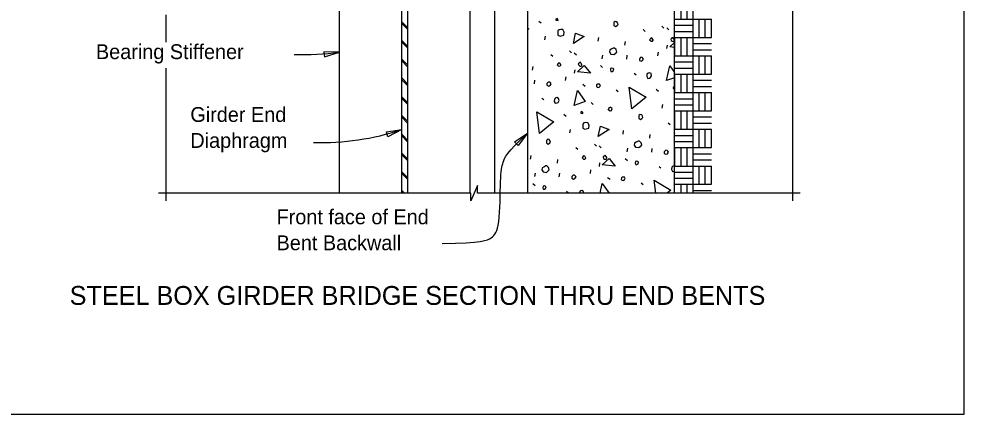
# Model space of a CAD drawing. Extents: x 112544 to 112597.1, y 111084 to 111107.1.
# Drawn here: x 112565.15 to 112574.78, y 111085.9 to 111089.92 of the extents above; entities that cross this region are included whole.
import ezdxf

# ---------------------------------------------------------------- set-up
doc = ezdxf.new("R2010")
doc.units = 0
for name, color, linetype in [('ActivePts-ConstElements', 7, 'Continuous'), ('Dimension', 7, 'Continuous'), ('Miscellaneous', 7, 'Continuous'), ('SteelGirder', 7, 'Continuous'), ('SupstrConc', 7, 'Continuous'), ('TextStructures', 7, 'Continuous')]:
    doc.layers.add(name, color=color, linetype=linetype)

msp = doc.modelspace()

# ---------------------------------------------------------------- linework, layer by layer
at = {"layer": 'ActivePts-ConstElements'}
msp.add_lwpolyline([(112543.9918, 111085.9039), (112574.7797, 111085.9039), (112574.7797, 111105.3634), (112543.9918, 111105.3634)], close=True, dxfattribs=at)
at = {"layer": 'Dimension'}
for points in [[(112573.0332, 111088.0729), (112573.0332, 111090.2426)], [(112566.6473, 111089.6865), (112566.6473, 111089.9653)], [(112566.6473, 111088.0729), (112566.6473, 111089.4223)], [(112573.1107, 111088.1504), (112569.8203, 111088.1504), (112569.8203, 111088.2279), (112569.7865, 111088.1504), (112569.7528, 111088.0729), (112569.7528, 111088.1504), (112566.5697, 111088.1504)]]:
    msp.add_lwpolyline(points, dxfattribs=at)
for points in [[(112568.413, 111089.5866), (112568.2547, 111089.5912), (112568.262, 111089.5388)], [(112569.0485, 111088.7986), (112568.9082, 111088.725), (112568.8918, 111088.7753)], [(112570.3297, 111088.7631), (112570.2358, 111088.6355), (112570.199, 111088.6735)]]:
    msp.add_lwpolyline(points, close=True, dxfattribs=at)
for centre, start, end in [((112568.0497, 111092.1885), 267.88954, 277.94853), ((112568.2255, 111091.2935), 268.34066, 288.25581)]:
    msp.add_arc(centre, 2.6271, start, end, dxfattribs=at)
msp.add_open_spline([(112569.4599, 111087.6403), (112569.8663, 111087.6456), (112569.9716, 111087.6958), (112570.0513, 111087.7852), (112570.0513, 111088.3406), (112570.0777, 111088.4633), (112570.1154, 111088.5614), (112570.3297, 111088.7631)], degree=3, dxfattribs=at)
at = {"layer": 'Miscellaneous'}
for p, q in [((112572.0185, 111089.9229), (112572.0185, 111090.2966)), ((112571.8922, 111090.1104), (112571.8922, 111089.9229)), ((112571.9547, 111090.1104), (112571.9547, 111089.9229)), ((112569.1109, 111089.8341), (112569.0485, 111089.8965)), ((112570.4465, 111089.9029), (112570.4699, 111089.8832)), ((112571.8297, 111089.9229), (112572.0185, 111089.9229)), ((112572.0185, 111089.5491), (112572.0185, 111089.9229)), ((112572.0185, 111089.9229), (112572.2047, 111089.9229)), ((112572.0797, 111089.7366), (112572.0797, 111089.9229)), ((112572.1422, 111089.7366), (112572.1422, 111089.9229)), ((112572.2047, 111089.7366), (112572.2047, 111089.9229)), ((112569.1109, 111089.8164), (112569.0485, 111089.8788)), ((112571.5105, 111089.8152), (112571.5308, 111089.7974)), ((112571.7003, 111089.8506), (112571.7212, 111089.8303)), ((112571.7491, 111089.8326), (112571.7701, 111089.8123)), ((112571.8297, 111089.8604), (112572.0185, 111089.8604)), ((112571.8297, 111089.7979), (112572.0185, 111089.7979)), ((112569.1109, 111089.6432), (112569.0485, 111089.7056)), ((112570.508, 111089.7123), (112570.514, 111089.7475)), ((112571.0504, 111089.6971), (112571.0558, 111089.7348)), ((112571.8297, 111089.7366), (112572.2047, 111089.7366)), ((112571.8297, 111089.7366), (112571.8297, 111089.5491)), ((112571.8922, 111089.7366), (112571.8922, 111089.5491)), ((112571.9547, 111089.7366), (112571.9547, 111089.5491)), ((112569.1109, 111089.6255), (112569.0485, 111089.6879)), ((112571.3227, 111089.6562), (112571.3282, 111089.6939)), ((112571.7508, 111089.6234), (112571.7569, 111089.6587)), ((112572.0185, 111089.6741), (112572.2047, 111089.6741)), ((112572.0185, 111089.6116), (112572.2047, 111089.6116)), ((112569.1109, 111089.4523), (112569.0485, 111089.5147)), ((112570.5687, 111089.5629), (112570.589, 111089.545)), ((112570.7585, 111089.5982), (112570.7795, 111089.578)), ((112570.8073, 111089.5803), (112570.8283, 111089.56)), ((112571.0928, 111089.5196), (112571.0988, 111089.5548)), ((112571.3421, 111089.5165), (112571.3475, 111089.5542)), ((112571.6593, 111089.5497), (112571.6647, 111089.5874)), ((112571.8297, 111089.5491), (112572.0185, 111089.5491)), ((112572.0185, 111089.5491), (112572.2047, 111089.5491)), ((112572.0185, 111089.1754), (112572.0185, 111089.5491)), ((112572.0797, 111089.3629), (112572.0797, 111089.5491)), ((112572.1422, 111089.3629), (112572.1422, 111089.5491)), ((112572.2047, 111089.3629), (112572.2047, 111089.5491)), ((112569.1109, 111089.4346), (112569.0485, 111089.497)), ((112570.3809, 111089.4039), (112570.3864, 111089.4416)), ((112571.0727, 111089.4495), (112571.0961, 111089.4299)), ((112571.8297, 111089.4866), (112572.0185, 111089.4866)), ((112571.8297, 111089.4241), (112572.0185, 111089.4241)), ((112569.1109, 111089.2613), (112569.0485, 111089.3237)), ((112570.7175, 111089.2974), (112570.7229, 111089.335)), ((112570.809, 111089.3711), (112570.8151, 111089.4063)), ((112571.4173, 111089.371), (112571.4369, 111089.3555)), ((112571.8297, 111089.3629), (112572.2047, 111089.3629)), ((112571.8297, 111089.3629), (112571.8297, 111089.1754)), ((112571.8922, 111089.3629), (112571.8922, 111089.1754)), ((112571.9547, 111089.3629), (112571.9547, 111089.1754)), ((112569.1109, 111089.2437), (112569.0485, 111089.3061)), ((112570.4003, 111089.2641), (112570.4057, 111089.3018)), ((112570.8934, 111089.2591), (112570.9192, 111089.2401)), ((112572.0185, 111089.3004), (112572.2047, 111089.3004)), ((112572.0185, 111089.2379), (112572.2047, 111089.2379)), ((112569.1109, 111089.0704), (112569.0485, 111089.1328)), ((112571.2345, 111089.203), (112571.2548, 111089.1851)), ((112571.642, 111089.2086), (112571.6653, 111089.189)), ((112571.8297, 111089.1754), (112572.0185, 111089.1754)), ((112572.0185, 111088.8016), (112572.0185, 111089.1754)), ((112572.0185, 111089.1754), (112572.2047, 111089.1754)), ((112572.0797, 111088.9891), (112572.0797, 111089.1754)), ((112572.1422, 111088.9891), (112572.1422, 111089.1754)), ((112572.2047, 111088.9891), (112572.2047, 111089.1754)), ((112569.1109, 111089.0527), (112569.0485, 111089.1151)), ((112570.4755, 111089.1186), (112570.4952, 111089.1032)), ((112570.9796, 111089.0725), (112571.0006, 111089.0523)), ((112571.7034, 111089.018), (112571.7095, 111089.0533)), ((112571.8297, 111089.1129), (112572.0185, 111089.1129)), ((112571.8297, 111089.0504), (112572.0185, 111089.0504)), ((112569.1109, 111088.8795), (112569.0485, 111088.9419)), ((112570.7002, 111088.9563), (112570.7236, 111088.9366)), ((112571.8297, 111088.9891), (112572.2047, 111088.9891)), ((112571.8297, 111088.9891), (112571.8297, 111088.8016)), ((112571.8922, 111088.9891), (112571.8922, 111088.8016)), ((112571.9547, 111088.9891), (112571.9547, 111088.8016)), ((112569.1109, 111088.8618), (112569.0485, 111088.9242)), ((112571.7641, 111088.8686), (112571.7844, 111088.8508)), ((112572.0185, 111088.9266), (112572.2047, 111088.9266)), ((112572.0185, 111088.8641), (112572.2047, 111088.8641)), ((112569.1109, 111088.6886), (112569.0485, 111088.751)), ((112570.7616, 111088.7657), (112570.7677, 111088.8009)), ((112571.304, 111088.7505), (112571.3094, 111088.7882)), ((112571.5764, 111088.7096), (112571.5818, 111088.7473)), ((112571.8297, 111088.8016), (112572.0185, 111088.8016)), ((112571.8297, 111088.7391), (112572.0185, 111088.7391)), ((112572.0185, 111088.8016), (112572.2047, 111088.8016)), ((112572.0185, 111088.4279), (112572.0185, 111088.8016)), ((112572.0797, 111088.6154), (112572.0797, 111088.8016)), ((112572.1422, 111088.6154), (112572.1422, 111088.8016)), ((112572.2047, 111088.6154), (112572.2047, 111088.8016)), ((112569.1109, 111088.6709), (112569.0485, 111088.7333)), ((112571.0122, 111088.6516), (112571.0331, 111088.6314)), ((112571.8297, 111088.6766), (112572.0185, 111088.6766)), ((112569.1109, 111088.4977), (112569.0485, 111088.5601)), ((112570.8223, 111088.6163), (112570.8426, 111088.5984)), ((112571.061, 111088.6336), (112571.0819, 111088.6134)), ((112571.3464, 111088.573), (112571.3525, 111088.6082)), ((112571.5957, 111088.5699), (112571.6011, 111088.6076)), ((112571.8297, 111088.6154), (112572.2047, 111088.6154)), ((112571.8297, 111088.6154), (112571.8297, 111088.4279)), ((112571.8922, 111088.6154), (112571.8922, 111088.4279)), ((112571.9547, 111088.6154), (112571.9547, 111088.4279)), ((112572.0185, 111088.5529), (112572.2047, 111088.5529)), ((112569.1109, 111088.48), (112569.0485, 111088.5424)), ((112570.3622, 111088.4982), (112570.3677, 111088.5359)), ((112570.6346, 111088.4573), (112570.64, 111088.495)), ((112571.0627, 111088.4245), (112571.0687, 111088.4597)), ((112571.3264, 111088.5029), (112571.3497, 111088.4833)), ((112572.0185, 111088.4904), (112572.2047, 111088.4904)), ((112569.1109, 111088.3067), (112569.0485, 111088.3691)), ((112569.1109, 111088.2891), (112569.0485, 111088.3515)), ((112570.4046, 111088.3206), (112570.4107, 111088.3559)), ((112570.6539, 111088.3175), (112570.6593, 111088.3552)), ((112570.9711, 111088.3508), (112570.9766, 111088.3884)), ((112571.6709, 111088.4244), (112571.6906, 111088.4089)), ((112571.8297, 111088.4279), (112572.0185, 111088.4279)), ((112571.8297, 111088.3654), (112572.0185, 111088.3654)), ((112572.0185, 111088.4279), (112572.2047, 111088.4279)), ((112572.0185, 111088.1504), (112572.0185, 111088.4279)), ((112572.0797, 111088.2416), (112572.0797, 111088.4279)), ((112572.1422, 111088.2416), (112572.1422, 111088.4279)), ((112572.2047, 111088.2416), (112572.2047, 111088.4279)), ((112571.147, 111088.3125), (112571.1728, 111088.2935)), ((112571.4882, 111088.2564), (112571.5085, 111088.2385)), ((112571.8297, 111088.3029), (112572.0185, 111088.3029)), ((112569.0764, 111088.1504), (112569.0485, 111088.1782)), ((112569.0587, 111088.1504), (112569.0485, 111088.1605)), ((112570.3846, 111088.2505), (112570.408, 111088.2309)), ((112570.7291, 111088.172), (112570.7488, 111088.1566)), ((112571.8297, 111088.2416), (112572.2047, 111088.2416)), ((112571.8922, 111088.2417), (112571.8922, 111088.1504)), ((112571.9547, 111088.2417), (112571.9547, 111088.1504)), ((112572.0185, 111088.1791), (112572.2047, 111088.1791))]:
    msp.add_line(p, q, dxfattribs=at)
for points in [[(112570.6204, 111089.9106), (112570.6417, 111089.9086), (112570.6391, 111089.9182), (112570.6311, 111089.929), (112570.6203, 111089.9209), (112570.6204, 111089.9106)], [(112571.211, 111089.8799), (112571.2107, 111089.8617), (112571.2273, 111089.8481), (112571.2429, 111089.8574), (112571.2531, 111089.8679), (112571.2498, 111089.88), (112571.2405, 111089.8956), (112571.224, 111089.899), (112571.2115, 111089.8878), (112571.211, 111089.8799)], [(112570.3297, 111089.8317), (112570.3436, 111089.8235), (112570.3297, 111089.8121)], [(112570.6393, 111089.8018), (112570.6406, 111089.7582), (112570.6614, 111089.7482), (112570.6735, 111089.7514), (112570.7, 111089.7586), (112570.7043, 111089.7908), (112570.69, 111089.8154), (112570.6711, 111089.8181), (112570.6518, 111089.8129), (112570.6393, 111089.8018)], [(112570.7979, 111089.6735), (112570.8209, 111089.7806), (112570.9083, 111089.7445), (112570.7979, 111089.6735)], [(112571.5747, 111089.7108), (112571.5889, 111089.6965), (112571.604, 111089.698), (112571.6117, 111089.7078), (112571.6104, 111089.7126), (112571.6017, 111089.7258), (112571.5901, 111089.7305), (112571.5824, 111089.7206), (112571.5747, 111089.7108)], [(112571.7937, 111089.7048), (112571.8035, 111089.6971), (112571.8169, 111089.6955), (112571.8253, 111089.7029), (112571.8251, 111089.7132), (112571.8194, 111089.7246), (112571.8114, 111089.7354), (112571.7982, 111089.7267), (112571.7898, 111089.7193), (112571.7937, 111089.7048)], [(112571.165, 111089.5881), (112571.1787, 111089.5659), (112571.2109, 111089.5616), (112571.2402, 111089.5875), (112571.2337, 111089.6117), (112571.2165, 111089.6278), (112571.2037, 111089.6269), (112571.1833, 111089.6163), (112571.1677, 111089.6069), (112571.165, 111089.5881)], [(112571.7803, 111089.6391), (112571.8297, 111089.685)], [(112571.8297, 111089.634), (112571.7803, 111089.6391)], [(112571.4706, 111089.5198), (112571.4703, 111089.5017), (112571.488, 111089.4935), (112571.5018, 111089.4998), (112571.5131, 111089.5157), (112571.505, 111089.5265), (112571.4982, 111089.5324), (112571.4873, 111089.5347), (112571.4825, 111089.5334), (112571.4706, 111089.5198)], [(112570.6329, 111089.4585), (112570.6471, 111089.4441), (112570.6622, 111089.4456), (112570.6699, 111089.4554), (112570.6687, 111089.4603), (112570.6599, 111089.4735), (112570.6483, 111089.4781), (112570.6406, 111089.4683), (112570.6329, 111089.4585)], [(112570.8385, 111089.3867), (112570.9089, 111089.4522), (112570.9715, 111089.3732), (112570.8385, 111089.3867)], [(112570.8519, 111089.4524), (112570.8618, 111089.4447), (112570.8751, 111089.4431), (112570.8835, 111089.4505), (112570.8833, 111089.4609), (112570.8777, 111089.4723), (112570.8696, 111089.4831), (112570.8564, 111089.4743), (112570.848, 111089.4669), (112570.8519, 111089.4524)], [(112571.1754, 111089.4045), (112571.1792, 111089.39), (112571.192, 111089.3908), (112571.2034, 111089.3965), (112571.2092, 111089.4136), (112571.2024, 111089.4195), (112571.1908, 111089.4242), (112571.1763, 111089.4203), (112571.1754, 111089.4045)], [(112571.7478, 111089.2965), (112571.7798, 111089.4474), (112571.8297, 111089.3799)], [(112571.5466, 111089.3616), (112571.5452, 111089.338), (112571.5552, 111089.3199), (112571.5727, 111089.3221), (112571.5842, 111089.3277), (112571.5948, 111089.3461), (112571.5889, 111089.3678), (112571.5712, 111089.376), (112571.5591, 111089.3728), (112571.5466, 111089.3616)], [(112571.8297, 111089.3259), (112571.7478, 111089.2965)], [(112570.5288, 111089.2675), (112570.5285, 111089.2493), (112570.5462, 111089.2411), (112570.56, 111089.2474), (112570.5713, 111089.2634), (112570.5632, 111089.2741), (112570.5565, 111089.2801), (112570.5455, 111089.2823), (112570.5407, 111089.281), (112570.5288, 111089.2675)], [(112571.0351, 111089.2324), (112571.0413, 111089.2288), (112571.057, 111089.2279), (112571.0696, 111089.239), (112571.0725, 111089.2475), (112571.0638, 111089.2607), (112571.0431, 111089.2604), (112571.0348, 111089.253), (112571.0325, 111089.242), (112571.0351, 111089.2324)], [(112571.3948, 111089.0104), (112571.3669, 111089.2307), (112571.539, 111089.1293), (112571.3948, 111089.0104)], [(112571.8297, 111089.2305), (112571.8265, 111089.2348), (112571.8157, 111089.2267), (112571.8159, 111089.2164)], [(112570.6048, 111089.1093), (112570.6034, 111089.0856), (112570.6134, 111089.0676), (112570.631, 111089.0697), (112570.6424, 111089.0754), (112570.653, 111089.0937), (112570.6472, 111089.1155), (112570.6294, 111089.1237), (112570.6174, 111089.1204), (112570.6048, 111089.1093)], [(112570.806, 111089.0441), (112570.8381, 111089.1951), (112570.9194, 111089.0849), (112570.806, 111089.0441)], [(112571.8159, 111089.2164), (112571.8297, 111089.215)], [(112571.1543, 111089.0003), (112571.1726, 111088.9897), (112571.1871, 111088.9936), (112571.1922, 111089.013), (112571.1732, 111089.0261), (112571.1649, 111089.0187), (112571.1558, 111089.0136), (112571.1543, 111089.0003), (112571.153, 111089.0051)], [(112570.4531, 111088.758), (112570.4251, 111088.9783), (112570.5972, 111088.8769), (112570.4531, 111088.758)], [(112570.8741, 111088.964), (112570.8953, 111088.962), (112570.8928, 111088.9716), (112570.8847, 111088.9824), (112570.8739, 111088.9743), (112570.8741, 111088.964)], [(112571.4647, 111088.9333), (112571.4644, 111088.9151), (112571.481, 111088.9015), (112571.4966, 111088.9108), (112571.5067, 111088.9213), (112571.5035, 111088.9334), (112571.4941, 111088.949), (112571.4777, 111088.9524), (112571.4651, 111088.9412), (112571.4647, 111088.9333)], [(112570.8929, 111088.8552), (112570.8942, 111088.8116), (112570.915, 111088.8016), (112570.9271, 111088.8048), (112570.9537, 111088.8119), (112570.958, 111088.8442), (112570.9436, 111088.8688), (112570.9248, 111088.8715), (112570.9054, 111088.8663), (112570.8929, 111088.8552)], [(112571.0515, 111088.7269), (112571.0746, 111088.834), (112571.1619, 111088.7979), (112571.0515, 111088.7269)], [(112571.8297, 111088.7659), (112571.8283, 111088.7642)], [(112571.8283, 111088.7642), (112571.8297, 111088.7628)], [(112570.5229, 111088.681), (112570.5226, 111088.6628), (112570.5392, 111088.6491), (112570.5548, 111088.6585), (112570.5649, 111088.669), (112570.5617, 111088.681), (112570.5523, 111088.6966), (112570.5359, 111088.7), (112570.5234, 111088.6889), (112570.5229, 111088.681)], [(112571.4186, 111088.6415), (112571.4323, 111088.6193), (112571.4646, 111088.615), (112571.4938, 111088.6409), (112571.4874, 111088.6651), (112571.4701, 111088.6812), (112571.4574, 111088.6803), (112571.437, 111088.6697), (112571.4213, 111088.6603), (112571.4186, 111088.6415)], [(112571.7242, 111088.5732), (112571.7239, 111088.555), (112571.7416, 111088.5469), (112571.7555, 111088.5532), (112571.7667, 111088.5691), (112571.7587, 111088.5799), (112571.7519, 111088.5858), (112571.7409, 111088.5881), (112571.7361, 111088.5868), (112571.7242, 111088.5732)], [(112570.8865, 111088.5119), (112570.9007, 111088.4975), (112570.9159, 111088.499), (112570.9236, 111088.5088), (112570.9223, 111088.5137), (112570.9136, 111088.5269), (112570.902, 111088.5315), (112570.8943, 111088.5217), (112570.8865, 111088.5119)], [(112571.0921, 111088.4401), (112571.1626, 111088.5056), (112571.2252, 111088.4266), (112571.0921, 111088.4401)], [(112571.1056, 111088.5058), (112571.1154, 111088.4981), (112571.1288, 111088.4965), (112571.1371, 111088.5039), (112571.137, 111088.5142), (112571.1313, 111088.5257), (112571.1232, 111088.5365), (112571.1101, 111088.5277), (112571.1017, 111088.5203), (112571.1056, 111088.5058)], [(112571.429, 111088.4579), (112571.4329, 111088.4434), (112571.4456, 111088.4442), (112571.457, 111088.4499), (112571.4628, 111088.467), (112571.456, 111088.4729), (112571.4444, 111088.4776), (112571.4299, 111088.4737), (112571.429, 111088.4579)], [(112570.4768, 111088.3891), (112570.4906, 111088.3669), (112570.5228, 111088.3626), (112570.5521, 111088.3886), (112570.5456, 111088.4127), (112570.5283, 111088.4288), (112570.5156, 111088.428), (112570.4952, 111088.4173), (112570.4796, 111088.408), (112570.4768, 111088.3891)], [(112571.8002, 111088.415), (112571.7988, 111088.3914), (112571.8088, 111088.3733), (112571.8264, 111088.3754), (112571.8297, 111088.3771)], [(112571.8297, 111088.4272), (112571.8249, 111088.4294), (112571.8128, 111088.4262), (112571.8002, 111088.415)], [(112570.7824, 111088.3209), (112570.7821, 111088.3027), (112570.7998, 111088.2945), (112570.8137, 111088.3008), (112570.8249, 111088.3168), (112570.8169, 111088.3275), (112570.8101, 111088.3335), (112570.7992, 111088.3357), (112570.7943, 111088.3344), (112570.7824, 111088.3209)], [(112571.2888, 111088.2857), (112571.2949, 111088.2822), (112571.3107, 111088.2813), (112571.3232, 111088.2924), (112571.3261, 111088.3009), (112571.3174, 111088.3141), (112571.2968, 111088.3138), (112571.2884, 111088.3064), (112571.2862, 111088.2954), (112571.2888, 111088.2857)], [(112571.6375, 111088.1505), (112571.6205, 111088.2841), (112571.7926, 111088.1826), (112571.7536, 111088.1505)], [(112570.4872, 111088.2056), (112570.4911, 111088.1911), (112570.5038, 111088.1919), (112570.5152, 111088.1975), (112570.521, 111088.2146), (112570.5143, 111088.2206), (112570.5027, 111088.2252), (112570.4882, 111088.2213), (112570.4872, 111088.2056)], [(112570.8585, 111088.1627), (112570.8577, 111088.1505)], [(112570.9057, 111088.1505), (112570.9008, 111088.1689), (112570.8831, 111088.177), (112570.871, 111088.1738), (112570.8585, 111088.1627)], [(112571.0709, 111088.1505), (112571.0917, 111088.2485), (112571.164, 111088.1505)]]:
    msp.add_lwpolyline(points, dxfattribs=at)
at = {"layer": 'SteelGirder'}
for p, q in [((112569.9964, 111088.1504), (112569.9964, 111092.6186)), ((112569.0485, 111088.1504), (112569.0485, 111092.5352)), ((112569.1109, 111088.1504), (112569.1109, 111092.5352)), ((112569.7464, 111088.1504), (112569.7464, 111092.3781)), ((112568.413, 111088.1504), (112568.413, 111091.5176))]:
    msp.add_line(p, q, dxfattribs=at)
at = {"layer": 'SupstrConc'}
for p, q in [((112570.3297, 111092.6186), (112570.3297, 111088.1505)), ((112571.8297, 111088.1504), (112571.8297, 111092.6186))]:
    msp.add_line(p, q, dxfattribs=at)

# ---------------------------------------------------------------- texts
at = {"layer": 'Dimension'}
for s, p in [('Girder End', (112566.894, 111088.8765)), ('Diaphragm', (112566.894, 111088.6125)), ('Front face of End ', (112567.7728, 111087.835)), ('Bent Backwall', (112567.7728, 111087.571))]:
    msp.add_text(s, height=0.1512, dxfattribs=at).set_placement(p)
at = {"layer": 'TextStructures'}
for s, height, p in [('Bearing Stiffener', 0.1512, (112565.9319, 111089.5155)), ('STEEL BOX GIRDER BRIDGE SECTION THRU END BENTS', 0.192, (112565.664, 111087.0148))]:
    msp.add_text(s, height=height, dxfattribs=at).set_placement(p)

doc.saveas('drawing.dxf')
